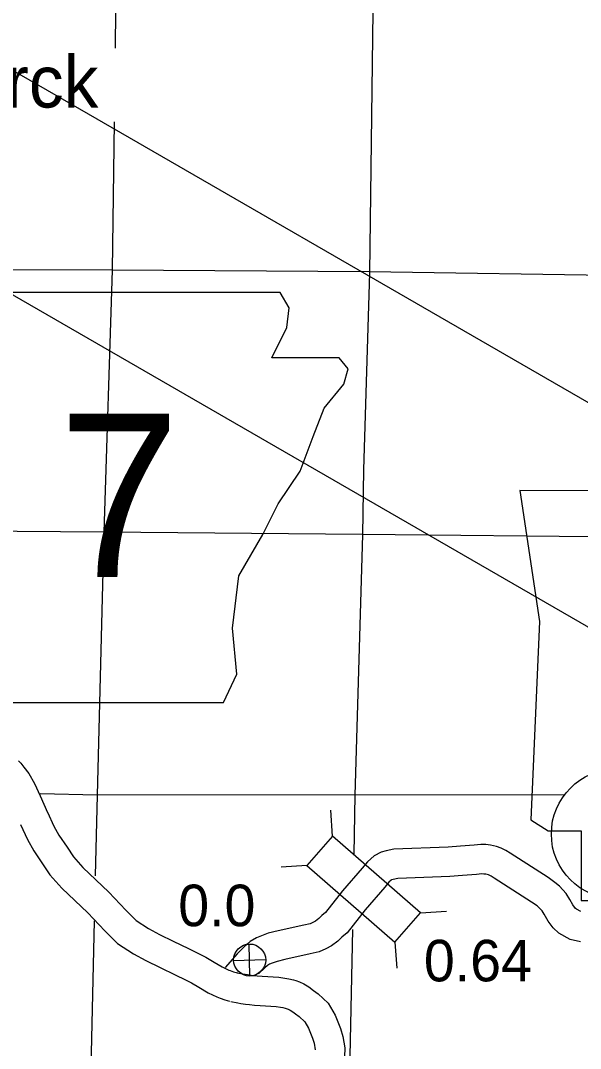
# Model space of a CAD drawing. Extents: x 369523 to 838377, y 495025 to 936819.
# Drawn here: x 558774 to 570168, y 828059 to 848990 of the extents above; entities that cross this region are included whole.
import ezdxf

# ---------------------------------------------------------------- set-up
doc = ezdxf.new("R2010")
doc.units = 0
for name, color, linetype in [('1', 7, 'Continuous'), ('21', 7, 'Continuous'), ('22', 7, 'Continuous'), ('DSN_BRDG_Annotation', 7, 'Continuous'), ('DSN_DRFT_Common-Annotations', 7, 'Continuous'), ('DSN_DRFT_Common-Line', 7, 'Continuous'), ('DSN_DRFT_Junk-No-Plot', 7, 'Continuous'), ('Level 1', 7, 'Continuous'), ('Level 21', 7, 'Continuous'), ('Level 22', 7, 'Continuous')]:
    doc.layers.add(name, color=color, linetype=linetype)

msp = doc.modelspace()

# ---------------------------------------------------------------- linework, layer by layer
at = {"layer": '21'}
for p, q in [((459282, 905322), (715348, 757482)), ((708796, 756692), (471020, 893972))]:
    msp.add_line(p, q, dxfattribs=at)
at = {"layer": '22'}
for points in [[(556068, 843454), (556468, 840789), (556290, 836748), (556646, 836526), (557312, 836526), (557312, 835105), (562907, 835105), (563174, 835682), (563085, 836615), (563218, 837680), (563707, 838524), (564018, 839146), (564462, 839812), (564728, 840523), (564950, 841100), (565350, 841588), (565439, 841899), (565261, 842121), (563884, 842121), (564195, 842743), (564240, 843143), (564056, 843450)], [(568936, 839418), (569336, 836754), (569158, 832713), (569514, 832491), (570180, 832491), (570180, 831069), (575775, 831069), (576042, 831647), (575953, 832579), (576086, 833645), (576575, 834489), (576886, 835111), (577330, 835777), (577596, 836487), (577818, 837065), (578218, 837553), (578307, 837864), (578129, 838086), (576752, 838086), (577063, 838708), (577108, 839108), (576924, 839415)]]:
    msp.add_lwpolyline(points, close=True, dxfattribs=at)
at = {"layer": 'DSN_DRFT_Common-Annotations'}
for p, q in [((563443, 829535), (563428, 830186)), ((563110, 829853), (563761, 829868))]:
    msp.add_line(p, q, dxfattribs=at)
msp.add_circle((563436, 829860), 326, dxfattribs=at)
at = {"layer": 'DSN_DRFT_Common-Line'}
msp.add_circle((570896, 832427), 1320, dxfattribs=at)
at = {"layer": 'Level 1'}
for points in [[(558732, 833915), (558776, 833865), (558842, 833788), (558942, 833661), (559059, 833455), (559175, 833200), (559322, 832865)], [(559320, 832870), (559451, 832584), (559554, 832400), (559720, 832155), (559848, 831961), (560043, 831744), (560567, 831244), (560919, 830874), (561128, 830667), (561377, 830504), (561601, 830382), (561880, 830247), (562188, 830095), (562395, 829991), (562541, 829921), (562711, 829818), (562875, 829719), (563009, 829656), (563041, 829644), (563108, 829621), (563196, 829596)], [(558775, 832620), (558916, 832311), (559043, 832085), (559221, 831821), (559372, 831593), (559612, 831326), (560142, 830819), (560491, 830454), (560749, 830198), (561069, 829989), (561326, 829848), (561617, 829708), (561921, 829558), (562131, 829453), (562254, 829393), (562401, 829304), (562593, 829189), (562768, 829107), (562833, 829080), (562930, 829048), (563029, 829019)], [(570174, 830846), (570086, 830893), (570067, 830912), (570013, 830983), (569950, 831092), (569879, 831216), (569742, 831363), (569647, 831441), (569508, 831538), (568736, 832035), (568651, 832088), (568556, 832140), (568462, 832173), (568338, 832200), (568246, 832211), (568143, 832212), (568002, 832200), (567724, 832180), (567474, 832160), (566368, 832119)], [(566368, 832119), (566214, 832081), (566112, 832056), (565970, 831983), (565831, 831857), (565728, 831727), (565328, 831269), (564981, 830830), (564907, 830765), (564842, 830702), (564776, 830654), (564721, 830623), (564665, 830598), (564539, 830571), (564014, 830457), (563816, 830404), (563678, 830354), (563573, 830311), (563447, 830237), (563334, 830138), (563180, 829987), (562940, 829705)], [(570168, 830231), (569959, 830280), (569726, 830405), (569616, 830514), (569513, 830649), (569430, 830791), (569392, 830859), (569330, 830925), (569285, 830962), (569174, 831039), (568412, 831529), (568348, 831570), (568311, 831590), (568297, 831595), (568241, 831607), (568205, 831611), (568164, 831612), (568050, 831602), (567770, 831581), (567509, 831560), (566451, 831521)], [(566451, 831521), (566357, 831498), (566323, 831490), (566315, 831486), (566271, 831446), (566189, 831343), (565790, 830885), (565419, 830416), (565315, 830324), (565229, 830242), (565101, 830148), (564989, 830085), (564851, 830024), (564666, 829984), (564155, 829873), (563995, 829831), (563894, 829794), (563840, 829772), (563800, 829748), (563742, 829698), (563619, 829577), (563618, 829576)], [(563172, 829602), (563294, 829577), (563346, 829570), (563438, 829555), (563500, 829547), (563589, 829538), (563694, 829530), (564031, 829508), (564155, 829493), (564233, 829479), (564325, 829457), (564376, 829440), (564449, 829414), (564537, 829372), (564643, 829312), (564736, 829242), (564830, 829168), (565032, 828984), (565179, 828736), (565282, 828465), (565331, 828304), (565371, 828074), (565361, 827704)], [(563053, 829014), (563195, 828985), (563259, 828976), (563351, 828961), (563433, 828951), (563536, 828941), (563650, 828931), (563975, 828911), (564063, 828900), (564109, 828892), (564161, 828879), (564182, 828872), (564217, 828859), (564261, 828839), (564315, 828808), (564371, 828767), (564441, 828711), (564562, 828601), (564637, 828475), (564714, 828271), (564747, 828165), (564770, 828031)]]:
    msp.add_lwpolyline(points, dxfattribs=at)
at = {"layer": 'Level 21'}
for p, q in [((565121, 832382), (565085, 832909)), ((564601, 831785), (564074, 831749)), ((566912, 830821), (567439, 830857)), ((566392, 830224), (566428, 829697))]:
    msp.add_line(p, q, dxfattribs=at)
msp.add_lwpolyline([(566912, 830821), (565121, 832382), (564601, 831785), (566392, 830224)], close=True, dxfattribs=at)
at = {"layer": 'Level 22'}
for points in [[(560743, 851486), (560708, 849210), (560697, 848428)], [(566024, 851664), (565943, 849183), (565873, 843853), (565754, 839842), (565731, 838517), (565579, 833214), (565556, 832017)], [(560677, 846927), (560636, 843904), (560470, 838573), (560330, 833217), (560293, 831573)], [(571167, 843790), (565865, 843871), (560636, 843904), (555199, 843924), (553971, 843930)], [(571075, 838473), (565733, 838523), (560470, 838573), (555163, 838614)], [(569838, 833217), (565593, 833222), (560330, 833217), (559172, 833243)], [(560273, 830658), (560213, 827966), (560118, 823999)], [(565526, 830482), (565477, 827902), (565462, 827265)]]:
    msp.add_lwpolyline(points, dxfattribs=at)

# ---------------------------------------------------------------- texts
at = {"layer": '1'}
msp.add_text('Bismarck', height=1056, dxfattribs=at).set_placement((554550, 847218))
at = {"layer": '22'}
msp.add_text('7', height=3326, dxfattribs=at).set_placement((559545, 837658))
at = {"layer": 'DSN_BRDG_Annotation'}
msp.add_text('0.0', height=844.8, dxfattribs=at).set_placement((561983, 830549))
at = {"layer": 'DSN_DRFT_Junk-No-Plot'}
msp.add_text('0.64', height=844.8, dxfattribs=at).set_placement((566982, 829426))

doc.saveas('drawing.dxf')
